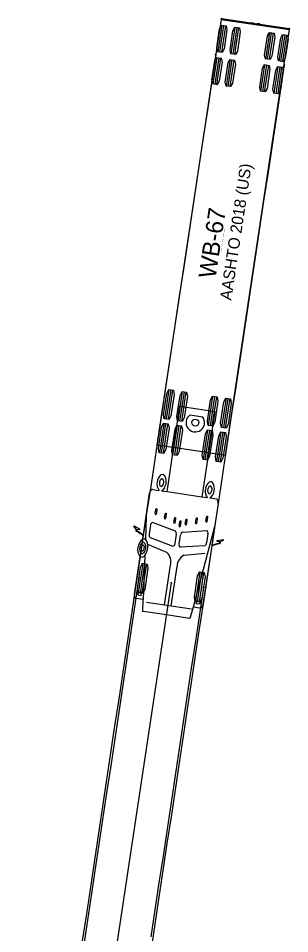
# Model space of a CAD drawing. Extents: x -69 to 14108008, y -6 to 8640172.
# Drawn here: x 14107923.9 to 14107957.2, y 8640059.7 to 8640172.2 of the extents above; entities that cross this region are included whole.
import ezdxf

# ---------------------------------------------------------------- set-up
doc = ezdxf.new("R2010")
doc.units = 0
doc.layers.add('AutoTurn4', color=7, linetype='Continuous')

msp = doc.modelspace()

# ---------------------------------------------------------------- linework, layer by layer
at = {"layer": 'AutoTurn4'}
for p, q in [((14107948.43, 8640168.05), (14107948.92, 8640171.31)), ((14107948.66, 8640168.01), (14107949.15, 8640171.27)), ((14107948.8, 8640172.04), (14107957.2, 8640170.78)), ((14107948.88, 8640167.98), (14107949.37, 8640171.24)), ((14107952.49, 8640171.56), (14107952.75, 8640171.52)), ((14107953.27, 8640171.44), (14107952.75, 8640171.52)), ((14107953.01, 8640171.48), (14107953, 8640171.41)), ((14107953.27, 8640171.44), (14107953.54, 8640171.4)), ((14107950.06, 8640167.8), (14107950.55, 8640171.06)), ((14107950.29, 8640167.77), (14107950.78, 8640171.03)), ((14107950.51, 8640167.73), (14107951, 8640171)), ((14107954.3, 8640167.16), (14107954.79, 8640170.43)), ((14107954.52, 8640167.13), (14107955.01, 8640170.39)), ((14107954.75, 8640167.1), (14107955.24, 8640170.36)), ((14107955.93, 8640166.92), (14107956.42, 8640170.18)), ((14107956.15, 8640166.88), (14107956.65, 8640170.15)), ((14107956.38, 8640166.85), (14107956.87, 8640170.11)), ((14107947.83, 8640164.09), (14107948.32, 8640167.35)), ((14107948.06, 8640164.06), (14107948.55, 8640167.32)), ((14107948.29, 8640164.02), (14107948.78, 8640167.29)), ((14107949.47, 8640163.84), (14107949.96, 8640167.11)), ((14107949.69, 8640163.81), (14107950.18, 8640167.07)), ((14107949.92, 8640163.78), (14107950.41, 8640167.04)), ((14107953.7, 8640163.21), (14107954.19, 8640166.47)), ((14107953.93, 8640163.17), (14107954.42, 8640166.44)), ((14107954.15, 8640163.14), (14107954.65, 8640166.4)), ((14107955.33, 8640162.96), (14107955.82, 8640166.23)), ((14107955.56, 8640162.93), (14107956.05, 8640166.19)), ((14107955.79, 8640162.89), (14107956.28, 8640166.16)), ((14107941.9, 8640122.93), (14107942.44, 8640126.56)), ((14107942.12, 8640122.9), (14107942.67, 8640126.52)), ((14107942.35, 8640122.86), (14107942.89, 8640126.49)), ((14107943.53, 8640122.69), (14107944.07, 8640126.31)), ((14107943.75, 8640122.65), (14107944.3, 8640126.28)), ((14107943.98, 8640122.62), (14107944.53, 8640126.24)), ((14107947.27, 8640122.12), (14107947.81, 8640125.75)), ((14107947.5, 8640122.09), (14107948.04, 8640125.72)), ((14107947.72, 8640122.06), (14107948.27, 8640125.68)), ((14107948.9, 8640121.88), (14107949.45, 8640125.5)), ((14107949.13, 8640121.84), (14107949.67, 8640125.47)), ((14107949.35, 8640121.81), (14107949.9, 8640125.44)), ((14107946.56, 8640123.17), (14107944.96, 8640123.41)), ((14107941.27, 8640118.78), (14107941.82, 8640122.4)), ((14107941.5, 8640118.74), (14107942.04, 8640122.37)), ((14107941.72, 8640118.71), (14107942.27, 8640122.34)), ((14107942.9, 8640118.53), (14107943.45, 8640122.16)), ((14107943.13, 8640118.5), (14107943.68, 8640122.13)), ((14107943.36, 8640118.47), (14107943.9, 8640122.09)), ((14107946.64, 8640117.97), (14107947.19, 8640121.6)), ((14107946.87, 8640117.94), (14107947.42, 8640121.56)), ((14107947.1, 8640117.9), (14107947.64, 8640121.53)), ((14107948.28, 8640117.73), (14107948.82, 8640121.35)), ((14107948.5, 8640117.69), (14107949.05, 8640121.32)), ((14107948.73, 8640117.66), (14107949.27, 8640121.28)), ((14107940.39, 8640114.29), (14107941.22, 8640114.17)), ((14107942.18, 8640114.02), (14107946.46, 8640113.38)), ((14107947.42, 8640113.24), (14107948.26, 8640113.11)), ((14107940.71, 8640111.39), (14107940.83, 8640111.93)), ((14107940.83, 8640111.93), (14107940.92, 8640111.91)), ((14107940.92, 8640111.91), (14107940.88, 8640111.37)), ((14107939.61, 8640110.93), (14107939.51, 8640108.13)), ((14107941.86, 8640110.83), (14107941.98, 8640111.37)), ((14107941.98, 8640111.37), (14107942.07, 8640111.35)), ((14107942.07, 8640111.35), (14107942.02, 8640110.8)), ((14107943.01, 8640110.32), (14107943.13, 8640110.85)), ((14107943.13, 8640110.85), (14107943.22, 8640110.84)), ((14107943.22, 8640110.84), (14107943.18, 8640110.29)), ((14107943.67, 8640109.91), (14107943.79, 8640110.44)), ((14107943.79, 8640110.44), (14107943.87, 8640110.43)), ((14107943.87, 8640110.43), (14107943.83, 8640109.88)), ((14107944.41, 8640110.11), (14107944.53, 8640110.64)), ((14107944.53, 8640110.64), (14107944.62, 8640110.63)), ((14107944.62, 8640110.63), (14107944.58, 8640110.08)), ((14107945.66, 8640110.23), (14107945.78, 8640110.79)), ((14107945.78, 8640110.79), (14107945.87, 8640110.78)), ((14107945.87, 8640110.78), (14107945.83, 8640110.21)), ((14107946.92, 8640110.46), (14107947.05, 8640110.99)), ((14107947.05, 8640110.99), (14107947.13, 8640110.98)), ((14107947.13, 8640110.98), (14107947.09, 8640110.43)), ((14107938.42, 8640109.37), (14107938.4, 8640109.38)), ((14107938.45, 8640109.36), (14107938.42, 8640109.37)), ((14107940.15, 8640109.89), (14107939.98, 8640108.77)), ((14107943.21, 8640109.15), (14107940.4, 8640110.23)), ((14107948.01, 8640109.67), (14107945.36, 8640099.82)), ((14107939.27, 8640108.71), (14107939.26, 8640108.61)), ((14107940.09, 8640108.38), (14107942.9, 8640107.31)), ((14107943.15, 8640107.64), (14107943.32, 8640108.76)), ((14107943.66, 8640107.57), (14107943.83, 8640108.68)), ((14107944.05, 8640109.03), (14107947.05, 8640109.23)), ((14107947.19, 8640108.83), (14107947.02, 8640107.71)), ((14107942.16, 8640106.52), (14107939.8, 8640107.51)), ((14107946.8, 8640107.37), (14107943.8, 8640107.17)), ((14107947.68, 8640107.44), (14107947.66, 8640107.35)), ((14107948.65, 8640107.83), (14107948.68, 8640107.82)), ((14107948.68, 8640107.82), (14107948.71, 8640107.84)), ((14107938.18, 8640101.43), (14107938.87, 8640106.02)), ((14107939.44, 8640106.16), (14107939.25, 8640100.74)), ((14107944.27, 8640106.2), (14107946.81, 8640106.46)), ((14107938.68, 8640101.57), (14107939.23, 8640105.2)), ((14107938.91, 8640101.54), (14107939.46, 8640105.16)), ((14107939.14, 8640101.5), (14107939.68, 8640105.13)), ((14107941.86, 8640100.12), (14107942.58, 8640104.96)), ((14107942.68, 8640099.99), (14107943.41, 8640104.83)), ((14107945.69, 8640100.52), (14107946.23, 8640104.14)), ((14107945.91, 8640100.48), (14107946.46, 8640104.11)), ((14107946.14, 8640100.45), (14107946.69, 8640104.08)), ((14107942.69, 8640102.82), (14107923.92, 8639978.08)), ((14107938.63, 8640101.68), (14107938.58, 8640101.33)), ((14107939.04, 8640101.62), (14107938.63, 8640101.68)), ((14107938.98, 8640101.26), (14107939.04, 8640101.62)), ((14107938.58, 8640101.33), (14107938.98, 8640101.26)), ((14107939.66, 8640100.45), (14107945.16, 8640099.62)), ((14107945.76, 8640100.24), (14107945.82, 8640100.6)), ((14107945.82, 8640100.6), (14107946.22, 8640100.53)), ((14107946.22, 8640100.53), (14107946.17, 8640100.18)), ((14107946.17, 8640100.18), (14107945.76, 8640100.24))]:
    msp.add_line(p, q, dxfattribs=at)
for points in [[(14107948.83, 8640172.11), (14107948.81, 8640172.11), (14107948.8, 8640172.04), (14107947.96, 8640166.44), (14107940.94, 8640119.77), (14107945.14, 8640119.14), (14107949.34, 8640118.51), (14107956.36, 8640165.18), (14107957.2, 8640170.78), (14107957.21, 8640170.85), (14107957.19, 8640170.85)], [(14107952.76, 8640171.59), (14107952.5, 8640171.63), (14107952.5, 8640171.63), (14107952.49, 8640171.56), (14107952.45, 8640171.57), (14107948.86, 8640172.11), (14107948.85, 8640172.11)], [(14107957.17, 8640170.86), (14107957.17, 8640170.86), (14107953.57, 8640171.4), (14107953.54, 8640171.4), (14107953.55, 8640171.47), (14107953.55, 8640171.47), (14107953.28, 8640171.51)], [(14107948.15, 8640167.73), (14107947.65, 8640164.43), (14107947.16, 8640161.13), (14107946.66, 8640157.83), (14107946.16, 8640154.53), (14107945.67, 8640151.23), (14107945.17, 8640147.93), (14107944.68, 8640144.63), (14107944.18, 8640141.33), (14107943.68, 8640138.03), (14107943.19, 8640134.73), (14107942.69, 8640131.43), (14107942.19, 8640128.13), (14107941.7, 8640124.83), (14107941.2, 8640121.53), (14107940.7, 8640118.23), (14107940.21, 8640114.93), (14107939.71, 8640111.63), (14107939.22, 8640108.33), (14107938.72, 8640105.03), (14107938.22, 8640101.73), (14107937.73, 8640098.43), (14107937.23, 8640095.13), (14107936.73, 8640091.83), (14107936.24, 8640088.53), (14107935.74, 8640085.23), (14107935.25, 8640081.93), (14107934.75, 8640078.63), (14107934.25, 8640075.33), (14107933.76, 8640072.03), (14107933.26, 8640068.73), (14107932.76, 8640065.43), (14107932.27, 8640062.13), (14107931.77, 8640058.83)], [(14107956.56, 8640166.47), (14107956.06, 8640163.17), (14107955.56, 8640159.87), (14107955.07, 8640156.57), (14107954.57, 8640153.27), (14107954.07, 8640149.97), (14107953.58, 8640146.67), (14107953.08, 8640143.37), (14107952.58, 8640140.07), (14107952.09, 8640136.77), (14107951.59, 8640133.47), (14107951.1, 8640130.17), (14107950.6, 8640126.87), (14107950.1, 8640123.57), (14107949.61, 8640120.27), (14107949.11, 8640116.97), (14107948.61, 8640113.67), (14107948.12, 8640110.37), (14107947.62, 8640107.07), (14107947.12, 8640103.77), (14107946.63, 8640100.47), (14107946.13, 8640097.17), (14107945.64, 8640093.87), (14107945.14, 8640090.57), (14107944.64, 8640087.27), (14107944.15, 8640083.97), (14107943.65, 8640080.67), (14107943.15, 8640077.37), (14107942.66, 8640074.07), (14107942.16, 8640070.77), (14107941.67, 8640067.47), (14107941.17, 8640064.17), (14107940.67, 8640060.87), (14107940.18, 8640057.57)], [(14107941.5, 8640114.13), (14107942.18, 8640114.02), (14107942.22, 8640114.26), (14107943.76, 8640124.51), (14107945.9, 8640124.18), (14107948.04, 8640123.86), (14107946.5, 8640113.62), (14107946.46, 8640113.38), (14107947.14, 8640113.28)], [(14107938.39, 8640109.3), (14107938.4, 8640109.38), (14107938.4, 8640109.39), (14107938.12, 8640109.67), (14107938.12, 8640109.67), (14107938.14, 8640109.79), (14107938.14, 8640109.79), (14107938.81, 8640109.43), (14107938.8, 8640109.33), (14107938.45, 8640109.36), (14107938.45, 8640109.36), (14107938.44, 8640109.28), (14107938.44, 8640109.28), (14107938.44, 8640109.28), (14107938.45, 8640109.24), (14107938.45, 8640109.24), (14107939.27, 8640108.71), (14107940.04, 8640113.83)], [(14107948.45, 8640112.56), (14107947.68, 8640107.44), (14107948.62, 8640107.71), (14107948.62, 8640107.71), (14107948.64, 8640107.75), (14107948.64, 8640107.75), (14107948.64, 8640107.75), (14107948.65, 8640107.83), (14107948.65, 8640107.83), (14107948.31, 8640107.9), (14107948.33, 8640108), (14107949.08, 8640108.14), (14107949.08, 8640108.14), (14107949.06, 8640108.03), (14107949.06, 8640108.02), (14107948.71, 8640107.84), (14107948.71, 8640107.83), (14107948.69, 8640107.75)], [(14107939.19, 8640108.18), (14107939.26, 8640108.6), (14107939.25, 8640108.62), (14107938.42, 8640109.16)], [(14107948.63, 8640107.62), (14107947.67, 8640107.35), (14107947.66, 8640107.34), (14107946.58, 8640100.16)], [(14107938.73, 8640103.42), (14107938.23, 8640100.12), (14107937.74, 8640096.82), (14107937.24, 8640093.52), (14107936.74, 8640090.22), (14107936.25, 8640086.92), (14107935.75, 8640083.62), (14107935.26, 8640080.32), (14107934.76, 8640077.02), (14107934.26, 8640073.72), (14107933.77, 8640070.42), (14107933.27, 8640067.12), (14107932.77, 8640063.82), (14107932.28, 8640060.52), (14107931.78, 8640057.22)], [(14107946.64, 8640102.23), (14107946.14, 8640098.93), (14107945.65, 8640095.63), (14107945.15, 8640092.33), (14107944.66, 8640089.03), (14107944.16, 8640085.73), (14107943.66, 8640082.43), (14107943.17, 8640079.13), (14107942.67, 8640075.83), (14107942.17, 8640072.53), (14107941.68, 8640069.23), (14107941.18, 8640065.93), (14107940.68, 8640062.63), (14107940.19, 8640059.33)], [(14107946.21, 8640099.69), (14107945.37, 8640099.82), (14107945.36, 8640099.82), (14107944.98, 8640098.43), (14107944.92, 8640098.44), (14107942.09, 8640098.87), (14107939.26, 8640099.29), (14107939.2, 8640099.3), (14107939.25, 8640100.74), (14107939.24, 8640100.74), (14107938.39, 8640100.87)]]:
    msp.add_lwpolyline(points, dxfattribs=at)
for points in [[(14107948.94, 8640167.97), (14107948.37, 8640168.05), (14107948.27, 8640168.54), (14107948.62, 8640170.89), (14107948.86, 8640171.32), (14107949.43, 8640171.23), (14107949.53, 8640170.75), (14107949.18, 8640168.4)], [(14107950.57, 8640167.72), (14107950, 8640167.81), (14107949.9, 8640168.29), (14107950.26, 8640170.64), (14107950.5, 8640171.07), (14107951.06, 8640170.99), (14107951.16, 8640170.5), (14107950.81, 8640168.15)], [(14107954.81, 8640167.09), (14107954.24, 8640167.17), (14107954.14, 8640167.65), (14107954.49, 8640170), (14107954.73, 8640170.43), (14107955.3, 8640170.35), (14107955.4, 8640169.87), (14107955.04, 8640167.52)], [(14107956.44, 8640166.84), (14107955.87, 8640166.93), (14107955.77, 8640167.41), (14107956.12, 8640169.76), (14107956.36, 8640170.19), (14107956.93, 8640170.1), (14107957.03, 8640169.62), (14107956.68, 8640167.27)], [(14107948.34, 8640164.01), (14107947.78, 8640164.1), (14107947.68, 8640164.58), (14107948.03, 8640166.93), (14107948.27, 8640167.36), (14107948.83, 8640167.28), (14107948.94, 8640166.79), (14107948.58, 8640164.44)], [(14107949.97, 8640163.77), (14107949.41, 8640163.85), (14107949.31, 8640164.34), (14107949.66, 8640166.69), (14107949.9, 8640167.12), (14107950.47, 8640167.03), (14107950.57, 8640166.55), (14107950.21, 8640164.2)], [(14107954.21, 8640163.13), (14107953.64, 8640163.22), (14107953.54, 8640163.7), (14107953.9, 8640166.05), (14107954.14, 8640166.48), (14107954.7, 8640166.39), (14107954.8, 8640165.91), (14107954.45, 8640163.56)], [(14107955.84, 8640162.89), (14107955.28, 8640162.97), (14107955.17, 8640163.45), (14107955.53, 8640165.8), (14107955.77, 8640166.23), (14107956.33, 8640166.15), (14107956.43, 8640165.67), (14107956.08, 8640163.32)], [(14107942.41, 8640122.86), (14107941.84, 8640122.94), (14107941.75, 8640123.47), (14107942.14, 8640126.08), (14107942.39, 8640126.57), (14107942.95, 8640126.48), (14107943.05, 8640125.95), (14107942.65, 8640123.34)], [(14107944.04, 8640122.61), (14107943.47, 8640122.7), (14107943.38, 8640123.23), (14107943.77, 8640125.84), (14107944.02, 8640126.32), (14107944.58, 8640126.24), (14107944.68, 8640125.7), (14107944.28, 8640123.09)], [(14107947.78, 8640122.05), (14107947.21, 8640122.13), (14107947.12, 8640122.67), (14107947.51, 8640125.28), (14107947.76, 8640125.76), (14107948.32, 8640125.67), (14107948.42, 8640125.14), (14107948.03, 8640122.53)], [(14107949.41, 8640121.8), (14107948.84, 8640121.89), (14107948.75, 8640122.42), (14107949.14, 8640125.03), (14107949.39, 8640125.51), (14107949.96, 8640125.43), (14107950.05, 8640124.89), (14107949.66, 8640122.28)], [(14107941.78, 8640118.7), (14107941.22, 8640118.79), (14107941.12, 8640119.32), (14107941.51, 8640121.93), (14107941.76, 8640122.41), (14107942.33, 8640122.33), (14107942.42, 8640121.79), (14107942.03, 8640119.18)], [(14107943.41, 8640118.46), (14107942.85, 8640118.54), (14107942.75, 8640119.08), (14107943.15, 8640121.69), (14107943.39, 8640122.17), (14107943.96, 8640122.08), (14107944.05, 8640121.55), (14107943.66, 8640118.94)], [(14107947.15, 8640117.89), (14107946.59, 8640117.98), (14107946.49, 8640118.51), (14107946.89, 8640121.12), (14107947.13, 8640121.61), (14107947.7, 8640121.52), (14107947.79, 8640120.99), (14107947.4, 8640118.38)], [(14107948.79, 8640117.65), (14107948.22, 8640117.73), (14107948.13, 8640118.27), (14107948.52, 8640120.88), (14107948.77, 8640121.36), (14107949.33, 8640121.27), (14107949.42, 8640120.74), (14107949.03, 8640118.13)], [(14107939.19, 8640101.5), (14107938.63, 8640101.58), (14107938.53, 8640102.11), (14107938.93, 8640104.72), (14107939.17, 8640105.21), (14107939.74, 8640105.12), (14107939.83, 8640104.59), (14107939.44, 8640101.98)], [(14107946.2, 8640100.44), (14107945.63, 8640100.53), (14107945.54, 8640101.06), (14107945.93, 8640103.67), (14107946.18, 8640104.15), (14107946.74, 8640104.07), (14107946.84, 8640103.53), (14107946.44, 8640100.92)]]:
    msp.add_lwpolyline(points, close=True, dxfattribs=at)
for centre, radius in [((14107948.85, 8640172.14), 0.0266), ((14107957.19, 8640170.89), 0.0266), ((14107948.15, 8640167.73), 0.0417), ((14107956.56, 8640166.47), 0.0417), ((14107945.64, 8640122.49), 0.424), ((14107938.73, 8640103.42), 0.0417), ((14107942.69, 8640102.82), 0.0417), ((14107946.64, 8640102.23), 0.0417)]:
    msp.add_circle(centre, radius, dxfattribs=at)
for centre, radius, start, end in [((14107949.13, 8640174.11), 2.02, 261.4466, 262.1303), ((14107952.76, 8640171.56), 0.0354, 85.7381, 257.9236), ((14107952.76, 8640171.56), 0.0352, 262.4209, 81.4213), ((14107953.28, 8640171.48), 0.0352, 81.4718, 260.4722), ((14107953.28, 8640171.48), 0.0353, 264.7827, 83.1324), ((14107957.19, 8640170.89), 0.0363, 280.524, 241.6854), ((14107945.64, 8640122.49), 1.14, 126.4466, 36.4466), ((14107941.6, 8640115.77), 0.346, 41.0408, 138.0539), ((14107942.07, 8640114.93), 1.14, 167.0253, 221.8166), ((14107942.37, 8640115.02), 1.42, 136.4506, 173.5184), ((14107941.76, 8640115.01), 0.522, 169.2771, 216.4412), ((14107941.91, 8640115.07), 0.664, 138.321, 176.5427), ((14107941.55, 8640115.4), 0.172, 53.9944, 141.145), ((14107941.04, 8640115.18), 0.732, 320.0383, 6.2727), ((14107941.4, 8640115.28), 0.362, 358.109, 47.15), ((14107940.94, 8640115.33), 1.14, 354.1618, 35.6826), ((14107940.34, 8640115.29), 1.73, 332.8214, 357.6199), ((14107948.03, 8640114.26), 1.14, 127.2105, 168.7313), ((14107947.53, 8640114.87), 0.346, 24.8393, 121.8523), ((14107946.57, 8640114.39), 1.42, 349.3747, 26.4426), ((14107940.65, 8640113.74), 0.619, 115.6069, 171.4486), ((14107941.47, 8640114.82), 0.169, 222.8935, 323.0122), ((14107941.22, 8640114.8), 0.729, 293.1241, 335.6381), ((14107948.59, 8640114.05), 1.73, 165.2732, 190.0717), ((14107947.89, 8640114.15), 0.732, 156.6204, 202.8548), ((14107947.57, 8640114.35), 0.362, 115.7431, 164.7841), ((14107947.38, 8640113.93), 0.169, 199.8809, 299.9996), ((14107947.47, 8640114.51), 0.172, 21.7482, 108.8988), ((14107946.83, 8640114.21), 1.14, 301.0765, 355.8678), ((14107947.15, 8640114.2), 0.522, 306.4519, 353.616), ((14107947.03, 8640114.3), 0.664, 346.3504, 24.5721), ((14107947.61, 8640113.83), 0.729, 187.255, 229.769), ((14107947.84, 8640112.66), 0.619, 351.4445, 47.2862), ((14107940.85, 8640111.31), 0.157, 150.7909, 237.9006), ((14107940.69, 8640111.35), 0.184, 292.6014, 4.4934), ((14107942, 8640110.75), 0.157, 150.7909, 237.9006), ((14107941.84, 8640110.79), 0.184, 292.6014, 4.4934), ((14107947.1, 8640110.39), 0.184, 158.3997, 230.2918), ((14107946.94, 8640110.4), 0.157, 284.9925, 12.1022), ((14107938.47, 8640109.22), 0.108, 134.4229, 180.6054), ((14107940.48, 8640109.9), 0.332, 104.1032, 182.5252), ((14107943.15, 8640110.24), 0.157, 150.7909, 237.9006), ((14107943, 8640110.28), 0.184, 292.6014, 4.4934), ((14107943.8, 8640109.83), 0.157, 150.7909, 237.9006), ((14107943.68, 8640109.85), 0.157, 284.9925, 12.1022), ((14107944.58, 8640110.04), 0.184, 158.3997, 230.2918), ((14107944.42, 8640110.05), 0.157, 284.9925, 12.1022), ((14107945.83, 8640110.19), 0.184, 158.3997, 230.2918), ((14107945.68, 8640110.2), 0.157, 284.9925, 12.1022), ((14107938.41, 8640109.21), 0.0522, 170.3292, 275.1838), ((14107940.09, 8640106.94), 1.53, 125.9393, 216.9483), ((14107939.3, 8640107.85), 0.347, 53.7738, 108.5844), ((14107940.35, 8640108.66), 0.387, 163.8817, 227.1137), ((14107942.94, 8640108.87), 0.387, 343.8842, 47.1113), ((14107944.22, 8640108.68), 0.387, 115.7819, 179.0089), ((14107946.87, 8640108.94), 0.332, 340.368, 58.79), ((14107939.42, 8640106.94), 0.634, 162.0304, 238.0321), ((14107939.84, 8640107.01), 1.03, 144.2702, 172.6567), ((14107939.58, 8640107.02), 0.589, 144.2021, 187.1848), ((14107939.27, 8640107.44), 0.317, 87.2968, 148.8892), ((14107939.24, 8640107.26), 0.17, 89.1156, 143.18), ((14107939.13, 8640107.2), 0.263, 350.3815, 64.2834), ((14107938.81, 8640107.14), 0.575, 324.5217, 1.092), ((14107939.12, 8640107.35), 0.44, 3.2408, 67.0536), ((14107938.38, 8640107.2), 1.19, 332.5778, 8.4671), ((14107938.11, 8640107.23), 1.7, 321.3672, 357.2753), ((14107938.69, 8640107.34), 1.14, 350.1511, 43.9537), ((14107942.86, 8640107.6), 0.296, 278.1653, 8.463), ((14107943.93, 8640107.44), 0.296, 154.4301, 244.7278), ((14107946.63, 8640107.72), 0.387, 295.7794, 359.0114), ((14107948.65, 8640107.67), 0.0522, 247.7093, 352.564), ((14107948.6, 8640107.7), 0.108, 342.2877, 28.4702), ((14107939.09, 8640106.4), 0.425, 239.5095, 326.0459), ((14107939.22, 8640106.94), 0.223, 178.6815, 248.284), ((14107939.09, 8640106.77), 0.366, 269.4989, 341.9799), ((14107939.14, 8640106.89), 0.158, 266.4178, 327.9305), ((14107941.13, 8640105.4), 1.52, 343.0266, 47.454), ((14107944.93, 8640104.83), 1.52, 115.4391, 179.8665), ((14107938.64, 8640101.28), 0.486, 163.0325, 238.9836), ((14107946.1, 8640100.16), 0.486, 283.9095, 359.8606)]:
    msp.add_arc(centre, radius, start, end, dxfattribs=at)
for centre, major_axis, start_param, end_param in [((14107938.4, 8640109.23), (-0.0116, -0.0774), 2.398717, 3.668019), ((14107938.4, 8640109.23), (-0.0116, -0.0774), 0.569648, 1.840391), ((14107948.66, 8640107.69), (0.0116, 0.0774), 1.301202, 2.571945), ((14107948.66, 8640107.69), (-0.0116, -0.0774), 2.615166, 3.884468)]:
    msp.add_ellipse(centre, major_axis=major_axis, ratio=0.544872, start_param=start_param, end_param=end_param, dxfattribs=at)

# ---------------------------------------------------------------- texts
for s, height, p in [('AASHTO 2018 (US)', 1.4167, (14107950.05, 8640137.45)), ('WB-67', 2.125, (14107948.12, 8640140.12)), ('(c) 2023 Transoft Solutions, Inc. All rights reserved.', 0.085, (14107948.86, 8640143.62))]:
    msp.add_text(s, height=height, rotation=81.4466, dxfattribs=at).set_placement(p)

doc.saveas('drawing.dxf')
